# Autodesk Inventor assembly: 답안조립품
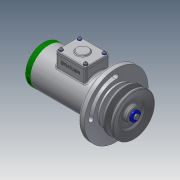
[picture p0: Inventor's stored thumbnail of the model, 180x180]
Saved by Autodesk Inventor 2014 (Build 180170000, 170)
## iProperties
Created: 2017-05
Part Number: 답안조립품
Document SubType Name: Assembly
Designer: user
Author: user
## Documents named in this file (20)
- C:\Users\user\Desktop\470508V1002\답안조립품.iam
- C:\Users\user\Desktop\470508V1002\본체.ipt
- C:\Users\user\Desktop\470508V1002\V-벨트풀리.ipt
- C:\Users\user\Desktop\470508V1002\너트 M10.ipt
- C:\Users\user\Desktop\470508V1002\멈춤링 15 x 1.ipt
- C:\Users\user\Desktop\470508V1002\멈춤링 35x1.6.ipt
- C:\Users\user\Desktop\470508V1002\베어링 15 x 35 x 11.ipt
- C:\Users\user\Desktop\470508V1002\볼트 M4 x 10.ipt
- C:\Users\user\Desktop\470508V1002\부시1.ipt
- C:\Users\user\Desktop\470508V1002\부시2.ipt
- C:\Users\user\Desktop\470508V1002\사이드 커버.ipt
- 사이드 커버.ipt
- C:\Users\user\Desktop\470508V1002\십자볼트 M3 x 10.ipt
- C:\Users\user\Desktop\470508V1002\오일 실 15 25 7.ipt
- C:\Users\user\Desktop\470508V1002\와셔 3x6.ipt
- C:\Users\user\Desktop\470508V1002\와셔 4x16.ipt
- C:\Users\user\Desktop\470508V1002\와셔 10x21.ipt
- C:\Users\user\Desktop\470508V1002\축.ipt
- C:\Users\user\Desktop\470508V1002\키 4 x 4 x 18.ipt
- C:\Users\user\Desktop\470508V1002\탑 커버.ipt
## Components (2 placed, 2 different names)
1. V-벨트풀리:1 — 각도:2
2. ISO 4017 M4 x 10:1 — 각도:3, 각도:4
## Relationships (3: Angle 3)
- 각도:2 [Angle]: V-벨트풀리:1
- 각도:3 [Angle]: ISO 4017 M4 x 10:1
- 각도:4 [Angle]: ISO 4017 M4 x 10:1
